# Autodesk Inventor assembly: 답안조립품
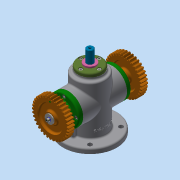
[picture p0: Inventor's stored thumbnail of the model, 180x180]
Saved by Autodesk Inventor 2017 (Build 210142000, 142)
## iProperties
Part Number: 답안조립품
Material: 일반
Document SubType Name: Assembly
Designer: mrc
Mass: 1861.36 g
Surface Area: 1735.36 cm^2
Volume: 520.954 cm^3
Density: 3.57299 g/cm^3
Author: mrc
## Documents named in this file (17)
- C:\Users\mrc\Desktop\600606V1009\답안조립품.iam
- C:\Users\mrc\Desktop\600606V1009\본체.ipt
- C:\Users\mrc\Desktop\600606V1009\가변스프링.ipt
- C:\Users\mrc\Desktop\600606V1009\멈춤링.ipt
- C:\Users\mrc\Desktop\600606V1009\베어링 6203.ipt
- C:\Users\mrc\Desktop\600606V1009\볼트 M4.ipt
- C:\Users\mrc\Desktop\600606V1009\부시.ipt
- C:\Users\mrc\Desktop\600606V1009\스퍼기어.ipt
- C:\Users\mrc\Desktop\600606V1009\스프링와셔.ipt
- C:\Users\mrc\Desktop\600606V1009\스프링조립용 와셔.ipt
- C:\Users\mrc\Desktop\600606V1009\슬라이더.ipt
- C:\Users\mrc\Desktop\600606V1009\오일 실 17 30 8.ipt
- C:\Users\mrc\Desktop\600606V1009\커버 A.ipt
- C:\Users\mrc\Desktop\600606V1009\커버 B.ipt
- C:\Users\mrc\Desktop\600606V1009\키 4x4x12.ipt
- C:\Users\mrc\Desktop\600606V1009\편심축.ipt
- C:\Users\mrc\Desktop\600606V1009\평와셔.ipt
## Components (1 placed, 1 different names)
1. 가변스프링:1
